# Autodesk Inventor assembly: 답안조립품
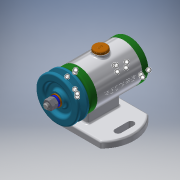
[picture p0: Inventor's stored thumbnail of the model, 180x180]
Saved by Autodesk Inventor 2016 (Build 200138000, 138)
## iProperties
Created: 2021-09
Part Number: 답안조립품
Material: 일반
Document SubType Name: Assembly
Designer: Windows7
Author: Windows7
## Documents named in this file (14)
- C:\Users\Windows7\Desktop\710906V1025\답안조립품.iam
- C:\Users\Windows7\Desktop\710906V1025\본체.ipt
- C:\Users\Windows7\Desktop\710906V1025\축.ipt
- C:\Users\Windows7\Desktop\710906V1025\키 3x3.ipt
- C:\Users\Windows7\Desktop\710906V1025\베어링 15x32x9.ipt
- C:\Users\Windows7\Desktop\710906V1025\뒤커버.ipt
- C:\Users\Windows7\Desktop\710906V1025\앞커버.ipt
- C:\Users\Windows7\Desktop\710906V1025\오일 실 15x25x7.ipt
- C:\Users\Windows7\Desktop\710906V1025\V벨트풀리.ipt
- C:\Users\Windows7\Desktop\710906V1025\너트 M8.ipt
- C:\Users\Windows7\Desktop\710906V1025\스프링와셔 8.ipt
- C:\Users\Windows7\Desktop\710906V1025\와셔 8x17.ipt
- C:\Users\Windows7\Desktop\710906V1025\캡.ipt
- C:\Users\Windows7\Desktop\710906V1025\볼트 M4x12.ipt
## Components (1 placed, 1 different names)
1. V벨트풀리:1
